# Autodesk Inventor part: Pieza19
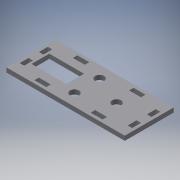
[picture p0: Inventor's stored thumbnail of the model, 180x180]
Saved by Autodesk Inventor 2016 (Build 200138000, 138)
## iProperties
Created: 2016-06
Part Number: Pieza19
Material: Genérico
Document SubType Name: Modeling
Designer: adm
Density: 1 g/cm^3
Appearance: Valor por defecto
Author: adm
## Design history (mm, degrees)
sketch "Boceto1"
  geometry: L1 (35, -11.5)-(-35, 11.5); L2 (-35, -11.5)-(28.913, 9.5); L3 (-40, 16.5)-(40, 16.5); L4 (40, 16.5)-(40, -16.5); L5 (40, -16.5)-(-40, -16.5); L6 (-40, -16.5)-(-40, 16.5); L7 (-15, 14.5)-(-15, 11.5); L8 (-15, -11.5)-(-15, -14.5); L9 (-23, 14.5)-(-23, 11.5); L10 (-23, -11.5)-(-23, -14.5); L11 (23, 14.5)-(23, 11.5); L12 (23, -11.5)-(23, -14.5); L13 (15, 14.5)-(15, 11.5); L14 (15, -11.5)-(15, -14.5); L15 (35, 9.5)-(38, 9.5); L16 (35, 3.5)-(38, 3.5); L17 (35, -3.5)-(38, -3.5); L18 (35, -9.5)-(38, -9.5); L19 (-38, 9.5)-(-35, 9.5); L20 (-38, 3.5)-(-35, 3.5); L21 (-38, -3.5)-(-35, -3.5); L22 (-38, -9.5)-(-35, -9.5); L23 (38, -9.5)-(38, -3.5); L24 (38, 3.5)-(38, 9.5); L25 (35, 9.5)-(35, 3.5); L26 (35, -3.5)-(35, -9.5); L27 (23, 14.5)-(15, 14.5); L28 (-15, 14.5)-(-23, 14.5); L29 (-23, 11.5)-(-15, 11.5); L30 (15, 11.5)-(23, 11.5); L31 (-35, -9.5)-(-35, -3.5); L32 (-35, 3.5)-(-35, 9.5); L33 (-38, 9.5)-(-38, 3.5); L34 (-38, -3.5)-(-38, -9.5); L35 (23, -11.5)-(15, -11.5); L36 (-15, -11.5)-(-23, -11.5); L37 (-23, -14.5)-(-15, -14.5); L38 (15, -14.5)-(23, -14.5); 1 further point
  constraints: 76 end point, 18 parallel, 10 horizontal, 9 perpendicular, 8 vertical, 2 horizontal alignment, 1 midpoint, 1 point on line
  dimensions: "d0" = 70 distance of L1.start L2.start; "d26" = 6 distance of L20.end L19.end; "d27" = 7 distance between parallel lines of L3 L19; "d28" = 6 distance of L16.end L15.end; "d29" = 33 distance between parallel lines of L5 L3; "d30" = 7 distance between parallel lines of L20 L21; "d31" = 7 distance between parallel lines of L5 L22; "d42" = 80 distance between parallel lines of L6 L4; "d43" = 2 distance from line of L5 L12.end; "d44" = 8 distance of L14.end L12.end; "d45" = 2 distance between parallel lines of L4 L23; "d46" = 6 distance between parallel lines of L17 L18
extrude "Extrusión1" new body sketch "Boceto1" distance "d12" = 3; taper "d13" = 0 deg
sketch "Boceto2"
  geometry: L1 (40, -16.5)-(40, 16.5) reference; L2 (40, 16.5)-(-40, 16.5) reference; L3 (-40, -16.5)-(40, -16.5) reference; L4 (-10, 6)-(-33.5, 6); L5 (-33.5, 6)-(-33.5, -6); L6 (-33.5, -6)-(-10, -6); L7 (-10, -6)-(-10, 6); L8 (35, 3.5)-(35, 9.5) reference; L9 (35, -3.5)-(35, -9.5) reference; L10 (35, -9.5)-(38, -9.5) reference; L11 (15, -11.5)-(23, -11.5) reference; L12 (-15, -11.5)-(-15, -14.5) reference; C1 r 3 at (18, 0); C2 r 3 at (-2, 8.5); C3 r 3 at (-2, -8.5); 2 further points
  constraints: 8 end point, 3 centre point, 2 parallel, 1 horizontal, 1 horizontal alignment, 1 midpoint, 1 perpendicular
  dimensions: "d15" = 6 diameter of C1; "d18" = 6 diameter of C2; "d19" = 6 diameter of C3; "d20" = 23.5 distance of L5.end L6.end; "d21" = 12 distance of L6.end L4.start; "d34" = 17 distance from line of L9 C1.centre; "d38" = 20 horizontal distance of C1.centre C3.centre; "d40" = 20 horizontal distance of C1.centre C2.centre; "d41" = 8 distance from line of C3.centre L7
extrude "Extrusión2" cut sketch "Boceto2" distance "d23" = 3; taper "d24" = 0 deg
node "Sólido1"
other parameters: "d2" = 3, "d3" = 2, "d4" = 8, "d5" = 8, "d6" = 15, "d7" = 15, "d8" = 6, "d9" = 6, "d10" = 3.5, "d11" = 3.5
